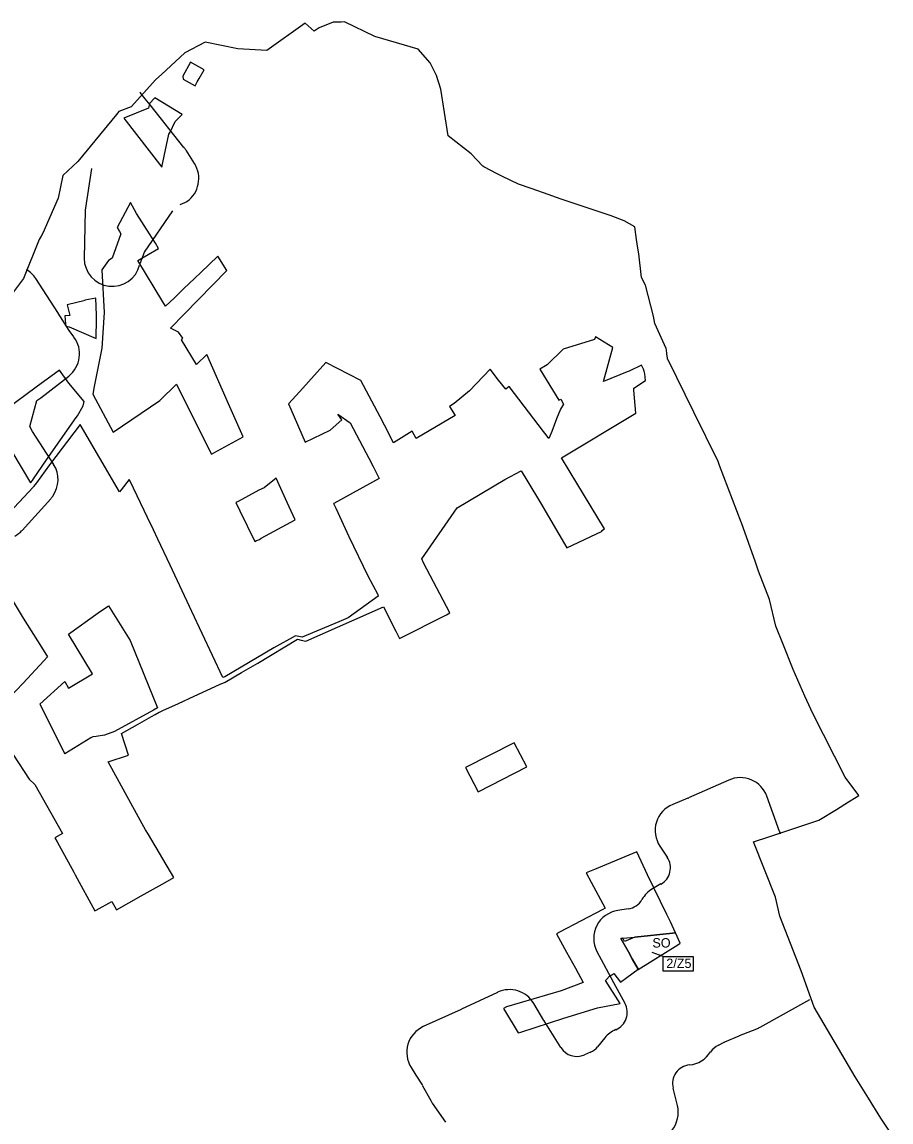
# Model space of a CAD drawing. Extents: x -445049 to -440454, y -1148980 to -1129741.
# Drawn here: x -441970 to -441045, y -1130912 to -1129741 of the extents above; entities that cross this region are included whole.
import ezdxf

# ---------------------------------------------------------------- set-up
doc = ezdxf.new("R2010")
doc.units = 0
for name, color, linetype in [('Vrstva 23', 7, 'Continuous'), ('Vrstva 3', 7, 'Continuous'), ('Vrstva 4', 7, 'Continuous'), ('Vrstva 5', 7, 'Continuous'), ('Vrstva 7', 7, 'Continuous'), ('Vrstva 8', 7, 'Continuous')]:
    doc.layers.add(name, color=color, linetype=linetype)

msp = doc.modelspace()

# ---------------------------------------------------------------- linework, layer by layer
at = {"layer": 'Vrstva 23'}
for p, q in [((-441839, -1129822.7), (-441843.2, -1129817.4)), ((-441833.8, -1129829.2), (-441839, -1129822.7)), ((-441786.5, -1129891.8), (-441795.5, -1129877.5)), ((-441801.6, -1129935.4), (-441794.4, -1129932.2)), ((-441931.8, -1130050.2), (-441955.3, -1130014.1)), ((-441931.7, -1130050.4), (-441931.8, -1130050.2)), ((-441950, -1130141.1), (-441920.3, -1130117.8)), ((-441961.8, -1130171.4), (-441954.1, -1130143.8)), ((-441937.4, -1130245.8), (-441937.3, -1130245.6)), ((-441970, -1130282.1), (-441939.4, -1130248.3)), ((-441217.9, -1130547.7), (-441260.7, -1130566.8)), ((-441261.4, -1130567.1), (-441277.5, -1130573.6)), ((-441163.9, -1130602.6), (-441177.5, -1130564.9)), ((-441162.8, -1130605.3), (-441163.6, -1130603.2)), ((-441291.2, -1130618.1), (-441283.4, -1130629.8)), ((-441290.1, -1130658.3), (-441299, -1130663.4)), ((-441325, -1130684.9), (-441336, -1130686.5)), ((-441358.2, -1130730), (-441349.3, -1130747.3)), ((-441349, -1130747.8), (-441349, -1130747.9)), ((-441348.9, -1130747.9), (-441340.6, -1130763.2)), ((-441464, -1130773.6), (-441502.4, -1130791.6)), ((-441340.6, -1130763.2), (-441328.5, -1130785.2)), ((-441414.6, -1130803.5), (-441425.5, -1130785.3)), ((-441184.7, -1130810.7), (-441131.6, -1130781.1)), ((-441502.6, -1130791.7), (-441543, -1130810.1)), ((-441396.6, -1130832.4), (-441414.4, -1130803.9)), ((-441222, -1130826.4), (-441207, -1130819.9)), ((-441206.4, -1130819.6), (-441188.2, -1130812.3)), ((-441349.9, -1130822), (-441357.6, -1130831.5)), ((-441229, -1130829.7), (-441222.7, -1130826.7)), ((-441222.7, -1130826.7), (-441222.6, -1130826.7)), ((-441365.1, -1130837.3), (-441371.6, -1130840.1)), ((-441556, -1130853.4), (-441550.8, -1130861.7)), ((-441550.8, -1130861.7), (-441544.3, -1130871.9)), ((-441543.7, -1130873), (-441535, -1130888.8)), ((-441272.6, -1130893.9), (-441277.2, -1130875.7)), ((-441533.4, -1130891.4), (-441519.4, -1130911.6))]:
    msp.add_line(p, q, dxfattribs=at)
for points in [[(-441797.5, -1129874.8), (-441797.7, -1129874.6), (-441833.8, -1129829.2)], [(-441896, -1129897.1), (-441902.8, -1129941.3), (-441903.9, -1129992.9)], [(-441844.1, -1129998.1), (-441839.8, -1129985.9), (-441809.6, -1129942)], [(-441914.8, -1130076.2), (-441919.9, -1130069.3), (-441931.4, -1130050.9)], [(-441936.3, -1130211.8), (-441958.7, -1130176.8), (-441961.8, -1130171.4)]]:
    msp.add_lwpolyline(points, dxfattribs=at)
for centre, radius, start, end in [((-441866.6, -1129836.1), 30, 38.5348, 42.9435), ((-441862.5, -1129841.4), 30, 38.5251, 38.5348), ((-441857.3, -1129847.9), 30, 38.515, 38.5251), ((-441820.9, -1129893.6), 30, 32.3998, 38.8939), ((-441811.9, -1129907.8), 30, 305.5727, 32.3998), ((-441873.9, -1129992.4), 30, 180, 345.8858), ((-441980.5, -1130030.5), 30, 33.0421, 59.3861), ((-441957, -1130066.6), 30, 33.0239, 33.0421), ((-441956.9, -1130066.8), 30, 31.9552, 33.0239), ((-441938.8, -1130094.2), 30, 308.1536, 36.662), ((-441968.5, -1130117.5), 30, 298.6149, 308.1536), ((-441961.6, -1130228), 30, 324.0476, 32.6196), ((-441961.7, -1130228.2), 30, 317.8838, 324.0476), ((-441992.3, -1130262), 30, 299.0496, 317.8838), ((-441205.7, -1130575.1), 30, 19.8756, 114.0681), ((-441266.3, -1130601.4), 30, 111.8887, 213.863), ((-441268.8, -1130548.6), 20, 291.8887, 294.0681), ((-441145.1, -1130595.8), 20, 199.8756, 201.8965), ((-441300, -1130641), 20, 299.5746, 33.863), ((-441284.2, -1130689.5), 30, 119.5746, 150.828), ((-441327.9, -1130665.1), 20, 278.3715, 330.828), ((-441331.6, -1130716.2), 30, 98.3715, 207.3788), ((-441322.6, -1130733.5), 30, 207.3788, 208.6105), ((-441322.6, -1130733.5), 30, 208.6105, 208.7436), ((-441451.2, -1130800.7), 30, 30.8394, 115.195), ((-441358.1, -1130772.8), 20, 28.7387, 28.7436), ((-441346, -1130794.9), 20, 292.8932, 28.7387), ((-441510.9, -1130773.5), 20, 294.3976, 295.195), ((-441397.4, -1130793.3), 20, 210.8394, 211.9952), ((-441530.6, -1130837.4), 30, 114.3976, 212.3277), ((-441326.6, -1130840.9), 30, 112.8932, 140.9676), ((-441199, -1130838.2), 20, 111.8014, 113.5493), ((-441199.3, -1130784.5), 30, 291.8014, 299.0745), ((-441379.6, -1130821.8), 20, 211.9952, 293.6839), ((-441373.1, -1130818.9), 20, 293.6839, 320.9676), ((-441220.4, -1130847.8), 20, 115.3872, 147.6276), ((-441235.6, -1130799.6), 30, 295.3872, 295.4234), ((-441214, -1130844.7), 20, 113.5493, 115.4234), ((-441262.7, -1130821), 30, 275.5879, 327.6276), ((-441257.8, -1130870.8), 20, 95.5879, 194.2307), ((-441567.7, -1130872.4), 20, 32.3223, 32.3277), ((-441561.2, -1130882.6), 20, 28.77, 32.3223), ((-441508.7, -1130874.3), 30, 208.77, 214.6415), ((-441301.7, -1130901.3), 30, 266.2055, 14.2307)]:
    msp.add_arc(centre, radius, start, end, dxfattribs=at)
at = {"layer": 'Vrstva 3'}
msp.add_line((-441287.6, -1130735.5), (-441299.6, -1130731.1), dxfattribs=at)
msp.add_lwpolyline([(-441287.6, -1130735.5), (-441255.9, -1130735.5), (-441255.9, -1130750.9), (-441287.6, -1130750.9)], close=True, dxfattribs=at)
at = {"layer": 'Vrstva 5'}
msp.add_lwpolyline([(-441045.4, -1130923.5), (-441056, -1130907.3), (-441069.4, -1130886.1), (-441083.5, -1130863.6), (-441127.2, -1130789.5), (-441140.8, -1130750.7), (-441163.5, -1130692.4), (-441168.2, -1130672.4), (-441191.8, -1130613.6), (-441185.2, -1130611.4), (-441181.8, -1130610.4), (-441129.5, -1130592.9), (-441122.3, -1130590.4), (-441103.5, -1130578.9), (-441090.6, -1130570.9), (-441082.4, -1130565.8), (-441079.4, -1130564), (-441094, -1130544.8), (-441128.6, -1130476.9), (-441137.2, -1130458.3), (-441149.4, -1130430), (-441160.5, -1130402.5), (-441167.9, -1130384), (-441174.5, -1130355.7), (-441186.2, -1130325.5), (-441189.5, -1130315.9), (-441204.4, -1130273.9), (-441204.7, -1130273.3), (-441227.8, -1130212.9), (-441228.5, -1130211), (-441229.4, -1130208.8), (-441255.1, -1130156.4), (-441282.6, -1130100.6), (-441283, -1130099.8), (-441283.1, -1130098.9), (-441283.8, -1130094.1), (-441284.4, -1130089.9), (-441284.6, -1130088.6), (-441296.5, -1130061.9), (-441297.9, -1130054), (-441306.5, -1130021.2), (-441310.8, -1130012.8), (-441313.8, -1129987.9), (-441314.7, -1129981.7), (-441316.2, -1129972.4), (-441318, -1129959), (-441329.4, -1129952.5), (-441343.1, -1129947.5), (-441396.3, -1129929.7), (-441415.2, -1129922.8), (-441428.1, -1129918.4), (-441441.6, -1129913.5), (-441458.7, -1129905.4), (-441464.5, -1129902.6), (-441478.6, -1129895.1), (-441479.6, -1129894.5), (-441492, -1129881.2), (-441516.7, -1129862.4), (-441524.5, -1129812.4), (-441528.8, -1129798.2), (-441535.8, -1129784.4), (-441548.5, -1129770), (-441594.4, -1129756.4), (-441627, -1129741.1), (-441630.5, -1129741.2), (-441638.8, -1129741.4), (-441653.7, -1129747.4), (-441655.8, -1129748.8), (-441659.1, -1129750.9), (-441668.7, -1129742.4), (-441709.6, -1129771.6), (-441740.4, -1129769.5), (-441775.2, -1129762.5), (-441796.7, -1129773.8), (-441821.7, -1129797), (-441827.5, -1129802.3), (-441853.9, -1129831.3), (-441867, -1129836.5), (-441869.5, -1129839.6), (-441910.7, -1129889.5), (-441926.7, -1129904.6), (-441931.7, -1129928.7), (-441948, -1129965.7), (-441949.7, -1129968.9), (-441951.6, -1129972.4), (-441968.3, -1130014.1), (-441981.3, -1130031.2)], dxfattribs=at)
at = {"layer": 'Vrstva 7'}
msp.add_line((-441951, -1130467), (-441924.5, -1130519.7), dxfattribs=at)
for points in [[(-441790.8, -1129783.9), (-441799, -1129798.7), (-441798.4, -1129801.8), (-441785.7, -1129808.9), (-441783.6, -1129804.9), (-441781.5, -1129801.2), (-441776.3, -1129791.9)], [(-441799.6, -1129839.7), (-441828.5, -1129821.8), (-441834.2, -1129827.9), (-441835.4, -1129832.8), (-441861.6, -1129843.4), (-441821.2, -1129895.7), (-441813.7, -1129860.6), (-441812.5, -1129858.2), (-441806.9, -1129847.1)], [(-441891.3, -1130035.1), (-441903, -1130037), (-441902.9, -1130037.5), (-441921.9, -1130042), (-441920.2, -1130049), (-441919.2, -1130053.3), (-441924.3, -1130053.6), (-441923.7, -1130062.1), (-441923.5, -1130064.6), (-441919.8, -1130065.4), (-441891.2, -1130077.8), (-441890.7, -1130056.9), (-441890.7, -1130052.9)], [(-441930, -1130111.7), (-441954.8, -1130129.8), (-441999.1, -1130162.3), (-442001.5, -1130163.9), (-441991.3, -1130181.4), (-441980.7, -1130198), (-441961, -1130231.5), (-441960.5, -1130231), (-441958.9, -1130228.8), (-441957.7, -1130227.2), (-441943.8, -1130207.1), (-441912.5, -1130162), (-441911.1, -1130160.1), (-441904.9, -1130149.6), (-441903.7, -1130144.9), (-441920, -1130125.4)], [(-441699.7, -1130226.5), (-441712.4, -1130236.7), (-441717.9, -1130239.3), (-441740, -1130251.2), (-441742.6, -1130252.4), (-441738.1, -1130261.4), (-441722.2, -1130293.7), (-441720.5, -1130292.9), (-441717.4, -1130291.6), (-441715.5, -1130290.5), (-441679.4, -1130270.8), (-441687.8, -1130252.4)], [(-441446.3, -1130508), (-441498.1, -1130534.5), (-441484.5, -1130560.1), (-441432.8, -1130533.7)], [(-441315.9, -1130624.2), (-441360.7, -1130642.8), (-441369.6, -1130646.5), (-441364.4, -1130656.2), (-441349.4, -1130684.2), (-441352, -1130685.6), (-441398, -1130709.5), (-441401.4, -1130711.5), (-441390.6, -1130730.9), (-441381.1, -1130748), (-441372.9, -1130763.1), (-441396.2, -1130772.1), (-441454.5, -1130789.1), (-441457.7, -1130790.7), (-441442.1, -1130816.7), (-441439.2, -1130815.8), (-441393.3, -1130801.2), (-441357.8, -1130789.9), (-441333.6, -1130785.6), (-441349, -1130761), (-441343.8, -1130755.3), (-441343.5, -1130755.8), (-441340.2, -1130753.4), (-441333.3, -1130762.9), (-441326.3, -1130757.8), (-441314.4, -1130749.1), (-441320.6, -1130737.8), (-441324.5, -1130730.6), (-441332.7, -1130716.4), (-441330.7, -1130716.1), (-441317.9, -1130714.8), (-441277.8, -1130710.5), (-441274.5, -1130710.2), (-441280, -1130698.6), (-441283.8, -1130690.7), (-441304.3, -1130648.4)]]:
    msp.add_lwpolyline(points, close=True, dxfattribs=at)
for points in [[(-441893.1, -1130129), (-441893.1, -1130129), (-441894.6, -1130137), (-441873.1, -1130177.4), (-441823.4, -1130144), (-441805.7, -1130126.4), (-441776.9, -1130184.1), (-441768.5, -1130200.9), (-441765.8, -1130199.4), (-441734.8, -1130182.5), (-441750.2, -1130147.4), (-441773.4, -1130094.9), (-441784.3, -1130105.6), (-441800.3, -1130079.2), (-441798.7, -1130077.5), (-441803.6, -1130071.3), (-441811.9, -1130066.9), (-441797.5, -1130052.1), (-441752.1, -1130005.5), (-441761.7, -1129990.2), (-441779.7, -1130007.5), (-441786.4, -1130013.9), (-441797.7, -1130024.7), (-441807.9, -1130034.5), (-441817.3, -1130043.6), (-441820.2, -1130038.8), (-441846.6, -1129995), (-441824.6, -1129982), (-441828.1, -1129976.5), (-441834.4, -1129966.6), (-441848.1, -1129944.7), (-441854.5, -1129933.2), (-441868.9, -1129959.8), (-441866.4, -1129964), (-441864.8, -1129966.4), (-441873.9, -1129992.4), (-441878, -1129994.9), (-441885.1, -1130004.7), (-441882.5, -1130050.1), (-441885.1, -1130088.2), (-441893.1, -1130129)], [(-441979, -1130521.4), (-441962.3, -1130546.6), (-441956.4, -1130552.4), (-441927, -1130604.7), (-441935, -1130609.1), (-441932.6, -1130613.4), (-441915, -1130645.8), (-441913.5, -1130648.5), (-441892.6, -1130686.8), (-441891.2, -1130686), (-441874.3, -1130676.8), (-441869.5, -1130685.9), (-441843.1, -1130671), (-441817.7, -1130656.6), (-441808.6, -1130651.4), (-441835.5, -1130605.5), (-441838.5, -1130600.5), (-441842.1, -1130594.2), (-441878.3, -1130528.2), (-441856.7, -1130521.4), (-441864.1, -1130498), (-441847, -1130488.5), (-441832.1, -1130480.1), (-441828.2, -1130477.9), (-441824.1, -1130475.6), (-441823, -1130475), (-441822.4, -1130474.7), (-441820.3, -1130473.7), (-441803.5, -1130466.1), (-441786.9, -1130458.4), (-441760, -1130446.1), (-441754, -1130443.4), (-441736.5, -1130433.2), (-441719.2, -1130423.3), (-441676.8, -1130397.9), (-441673, -1130398.8), (-441668.1, -1130400.1), (-441585.3, -1130363.5), (-441572.3, -1130389.4), (-441568.4, -1130397.1), (-441518.3, -1130371.8), (-441514.6, -1130369.9), (-441542.8, -1130316.5), (-441544.6, -1130312.3), (-441507.1, -1130258.1), (-441456.3, -1130227.9), (-441439, -1130218.7), (-441431.9, -1130230.3), (-441418.4, -1130252.7), (-441390.2, -1130300.5), (-441352.7, -1130282.9), (-441353.1, -1130282.1), (-441350.1, -1130280.5), (-441379.8, -1130231.7), (-441396.1, -1130204.8), (-441317, -1130157.2), (-441318.9, -1130133), (-441318.9, -1130130.8), (-441306.5, -1130122.4), (-441307.4, -1130115.4), (-441307.9, -1130112.8), (-441308.8, -1130110.5), (-441310.8, -1130106.4), (-441324.1, -1130112.5), (-441326.1, -1130113.3), (-441351.4, -1130123.6), (-441341.2, -1130087.4), (-441359.7, -1130076), (-441360.8, -1130079.1), (-441394.2, -1130089.2), (-441411.1, -1130106), (-441413, -1130107), (-441418.9, -1130110.5), (-441398.7, -1130143.4), (-441396.8, -1130142.5), (-441394, -1130147.9), (-441397, -1130152.9), (-441401.1, -1130163.3), (-441406.3, -1130176.7)], [(-441406.3, -1130176.7), (-441409.3, -1130184.4), (-441412.2, -1130180.5), (-441415, -1130176.8), (-441451.5, -1130129.1), (-441455.1, -1130131.9), (-441463, -1130122.1), (-441472, -1130110.5), (-441493.8, -1130133.5), (-441510.1, -1130146.9), (-441515.2, -1130150.1), (-441509.1, -1130159.7), (-441550.5, -1130184.1), (-441554.8, -1130176.6), (-441574.6, -1130188.8), (-441584.2, -1130170.2), (-441588.8, -1130161.3), (-441609.4, -1130122.5), (-441646.7, -1130103.5), (-441674.4, -1130134.2), (-441686.4, -1130147.5), (-441683.9, -1130152.9), (-441668.7, -1130188.3), (-441642, -1130175.4), (-441629.6, -1130164.3), (-441633.8, -1130158.3), (-441621, -1130167.6), (-441601.1, -1130205.2), (-441596.4, -1130214.2), (-441590, -1130226.7), (-441638.3, -1130253.4), (-441638.6, -1130253.5), (-441636.2, -1130258.5), (-441622.1, -1130288.4), (-441602.2, -1130330.4), (-441591.4, -1130350.1), (-441591, -1130351.9), (-441622.9, -1130375), (-441632.9, -1130379.2), (-441672, -1130395.7), (-441679, -1130394.2), (-441702.1, -1130406.9), (-441754.3, -1130437.8), (-441756.4, -1130438.7), (-441789.4, -1130368.3), (-441812.5, -1130319.1), (-441825.5, -1130291.3), (-441830.2, -1130281.3), (-441836.3, -1130268.4), (-441854.8, -1130229.7), (-441856, -1130227.8), (-441864.6, -1130238.9), (-441866.3, -1130241.2), (-441908.2, -1130169.3), (-441940.6, -1130212.4), (-441954.7, -1130231.4), (-441956.1, -1130233.2), (-441957.7, -1130235.4), (-441958.2, -1130235.9), (-441988.2, -1130268.3)], [(-442003.1, -1130318.6), (-441968.9, -1130375.5), (-441949.3, -1130406.2), (-441942.8, -1130416.6), (-441946.7, -1130420.8), (-441968.9, -1130444.5), (-441983.5, -1130460.3)], [(-441951, -1130467), (-441924.5, -1130442.9), (-441920.4, -1130450.1), (-441895.1, -1130434.6), (-441920.4, -1130392.4), (-441889.1, -1130369.8), (-441878, -1130362.4)], [(-441878, -1130362.4), (-441854.8, -1130399.3), (-441826, -1130470.9)], [(-441826, -1130470.9), (-441830.2, -1130473.2), (-441871.5, -1130496), (-441882.4, -1130500), (-441891.1, -1130501.3), (-441894.7, -1130501.8), (-441896.6, -1130502.9), (-441924.5, -1130519.7)]]:
    msp.add_lwpolyline(points, dxfattribs=at)
at = {"layer": 'Vrstva 8'}
msp.add_lwpolyline([(-441274.5, -1130710.2), (-441277.8, -1130710.5), (-441317.9, -1130714.8), (-441328.8, -1130719.5), (-441330.7, -1130716.1), (-441332.7, -1130716.4), (-441324.5, -1130730.6), (-441320.6, -1130737.8), (-441314.4, -1130749.1), (-441314.2, -1130749.4), (-441272.1, -1130723), (-441269.6, -1130721.4)], close=True, dxfattribs=at)

# ---------------------------------------------------------------- texts
at = {"layer": 'Vrstva 3'}
msp.add_text('2/Z5', height=10, dxfattribs=at).set_placement((-441284.4, -1130747.7))
at = {"layer": 'Vrstva 4'}
msp.add_text('SO', height=10, dxfattribs=at).set_placement((-441299.2, -1130725.9))

doc.saveas('drawing.dxf')
